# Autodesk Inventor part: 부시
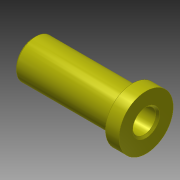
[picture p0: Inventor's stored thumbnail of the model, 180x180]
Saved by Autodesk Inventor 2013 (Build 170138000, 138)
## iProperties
Created: 2016-11
Part Number: 부시
Material: 강철, 연강
Document SubType Name: Modeling
Designer: mduedu
Density: 1 g/cm^3
Author: mduedu
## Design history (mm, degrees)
sketch "스케치1"
  geometry: L1 (0, 0)-(58, 0); L2 (58, 0)-(58, 14); L3 (58, 14)-(51, 14); L4 (51, 14)-(51, 10); L5 (51, 10)-(0, 10); L6 (0, 10)-(0, 0)
  constraints: 12 end point, 3 parallel, 2 perpendicular, 1 horizontal
  dimensions: "d0" = 58 distance of L1.start L1.end; "d1" = 7 distance of L2.end L3.end; "d2" = 28 diameter of L3 L1; "d3" = 20 diameter of L5 L1
revolve "회전1" sketch "스케치1" stored, may be unused: angle "d4" = 90 deg
hole "구멍1" diameter "d7" = 12; stored, may be unused: countersink angle "d11" = 90 deg, drill point angle "d13" = 118 deg; dims "d5" = 10, "d6" = 10, "d8" = 6, "d9" = 4, "d10" = 2, "d12" = 8
chamfer "모따기1" distance "d14" = 1; stored, may be unused: second distance "d15" = 2, angle "d16" = 45 deg
node "솔리드1"
